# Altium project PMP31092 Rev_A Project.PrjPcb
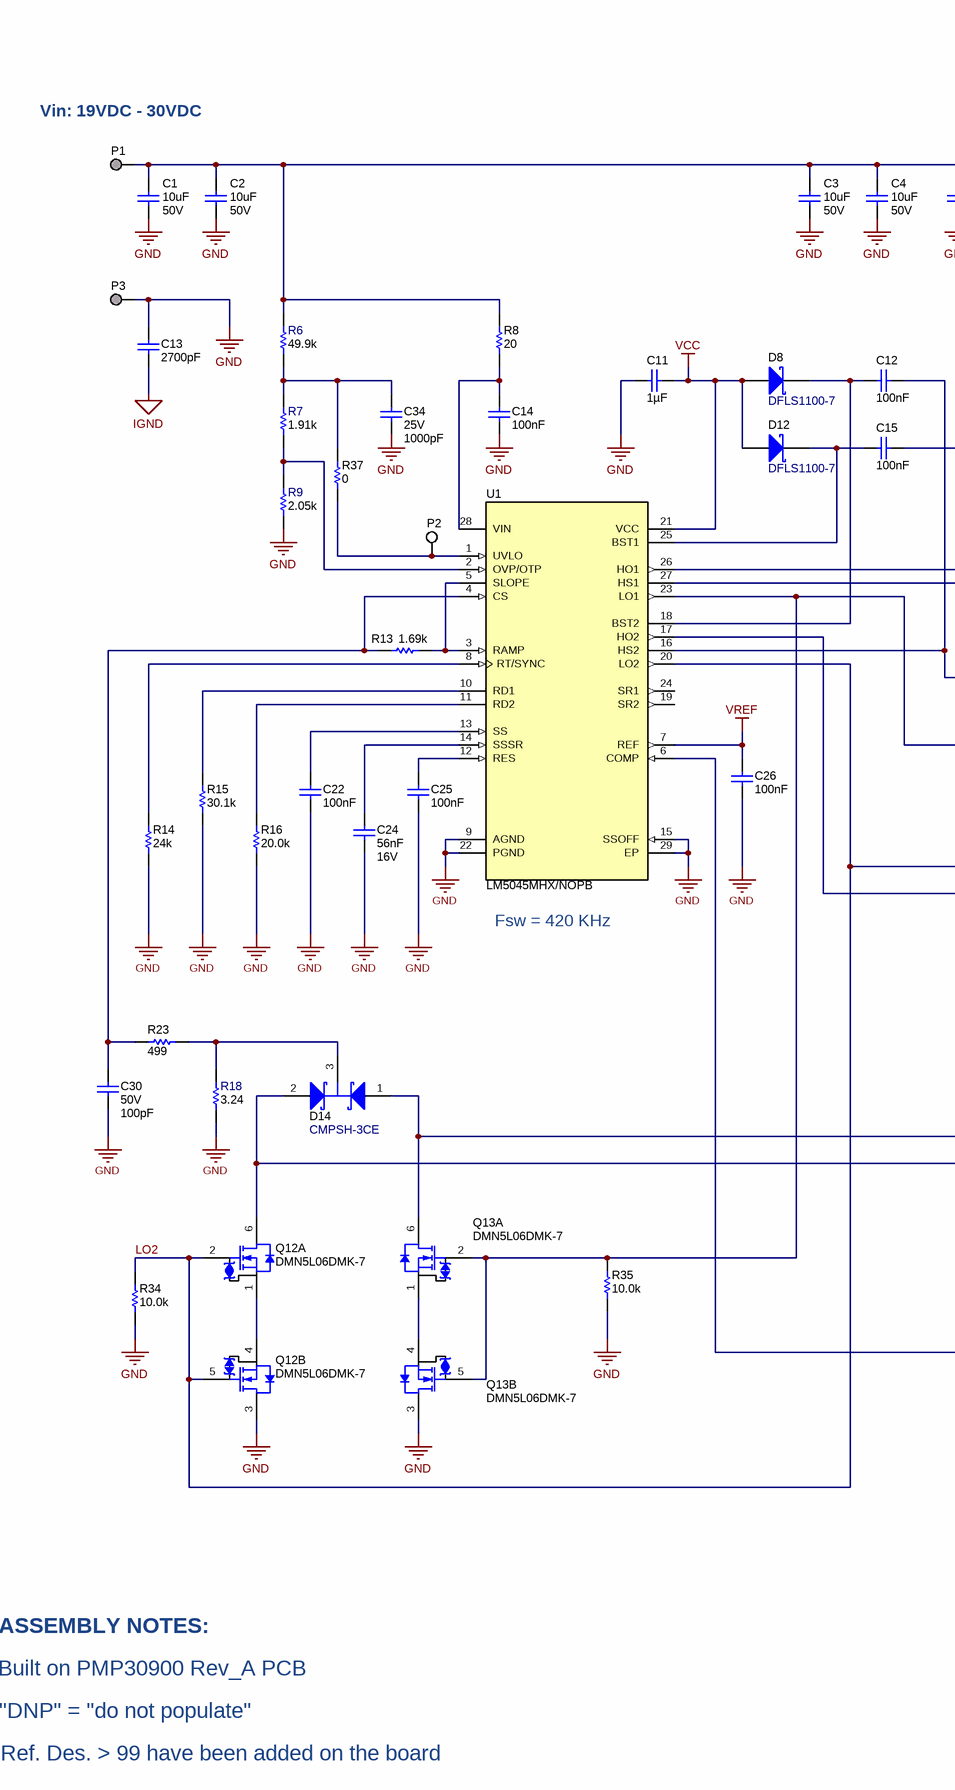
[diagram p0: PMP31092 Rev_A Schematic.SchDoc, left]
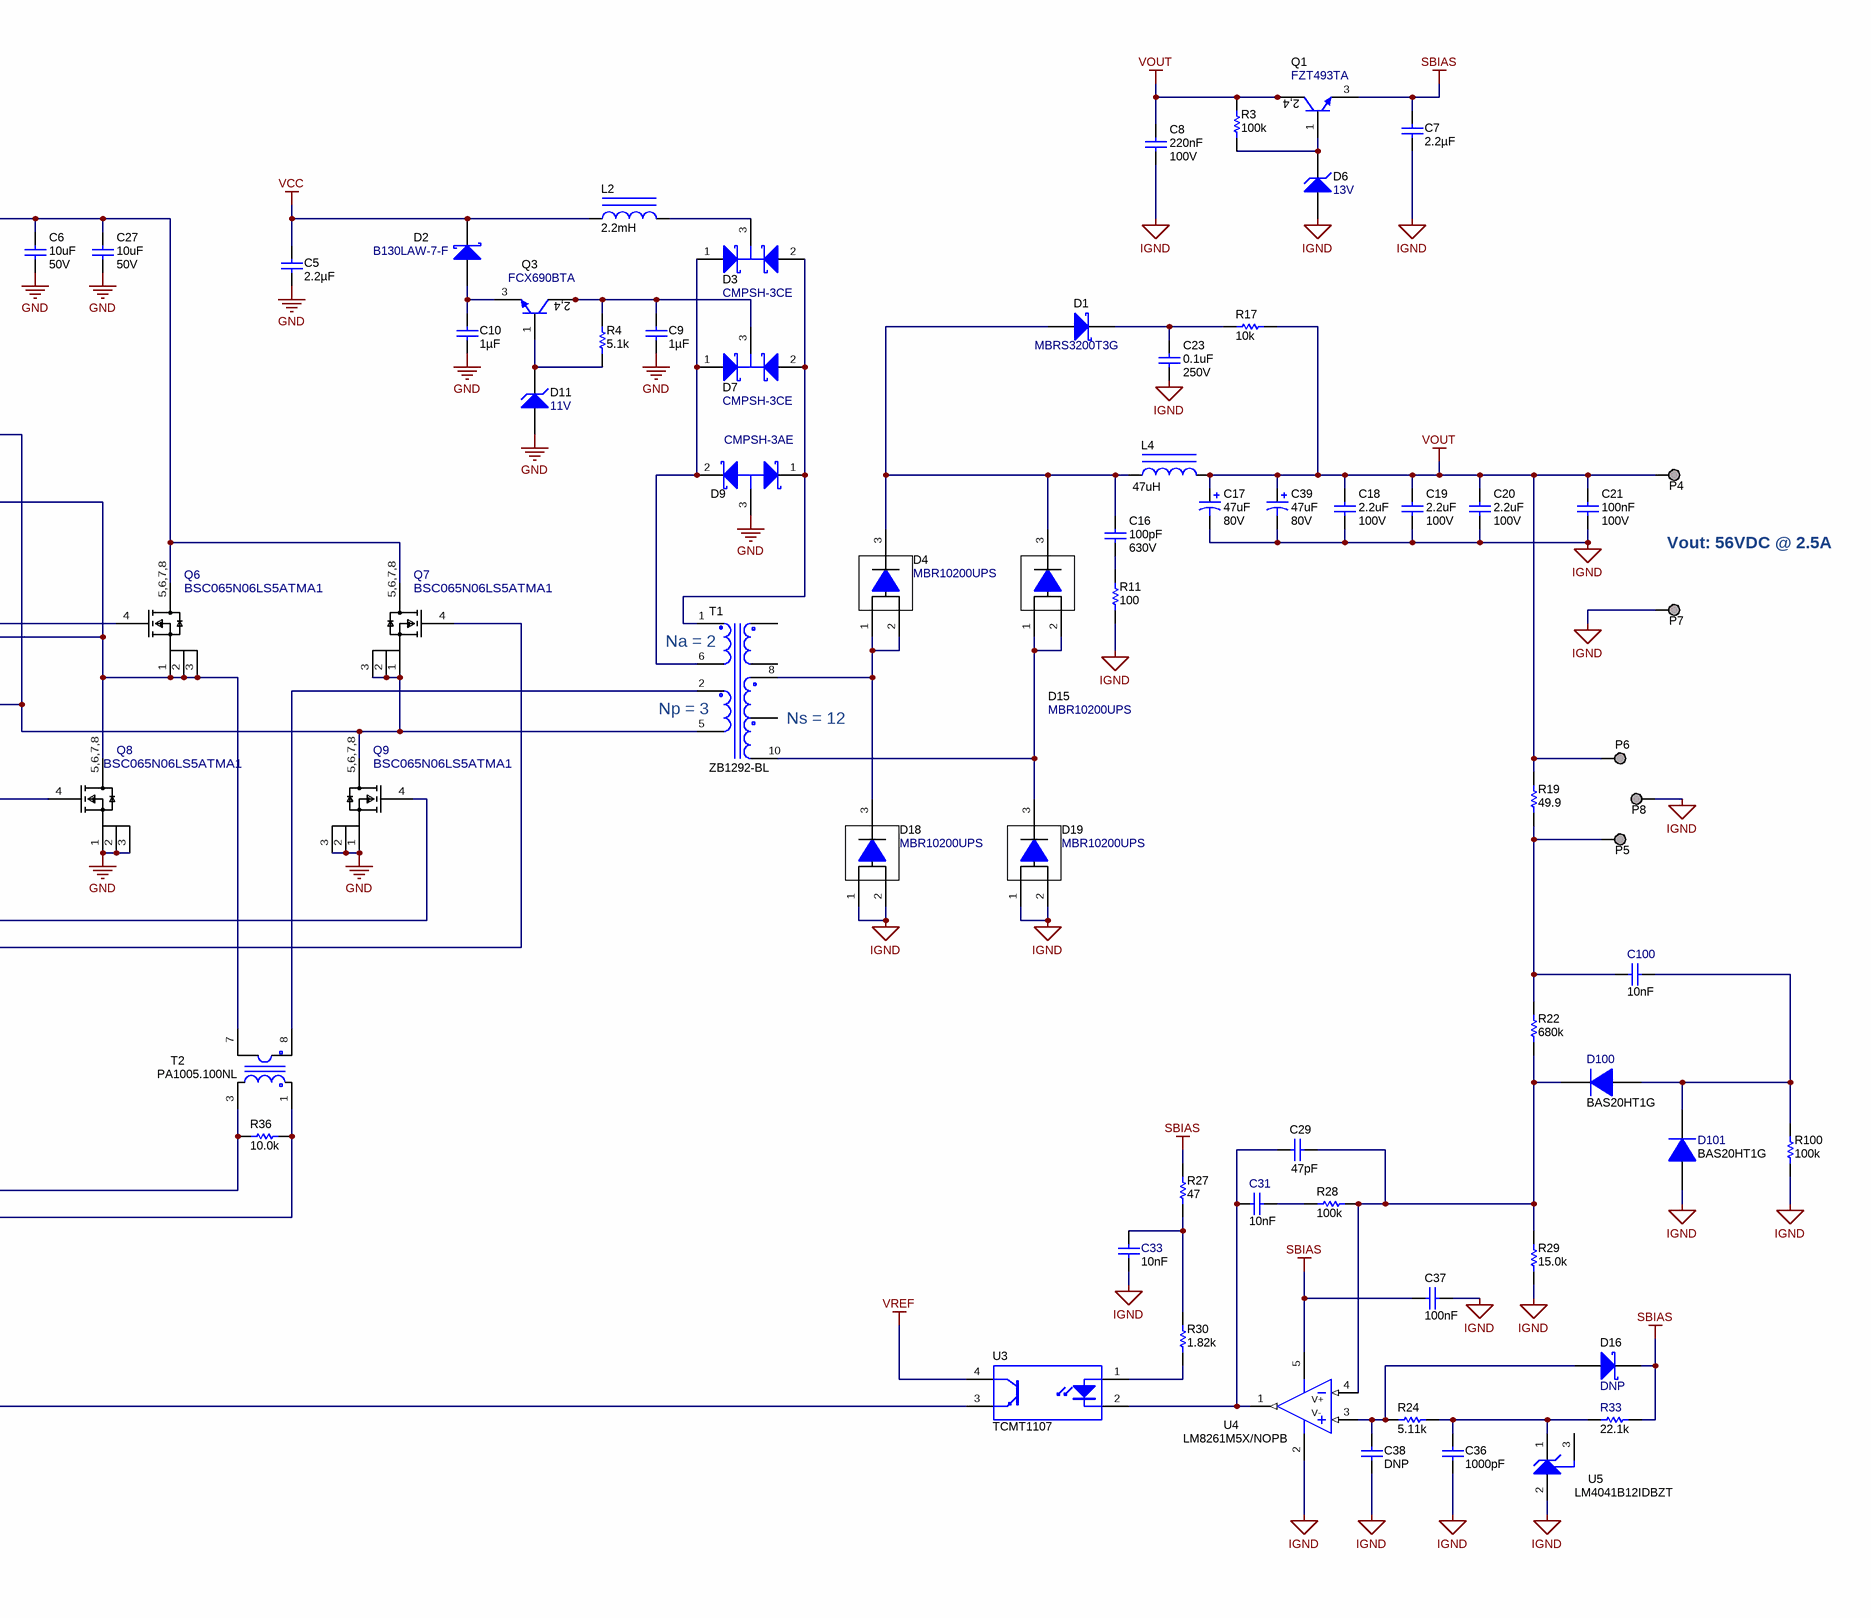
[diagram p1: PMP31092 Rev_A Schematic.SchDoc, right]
CopyrightYear: 2021; PCB_Layout: Renate Flesch; PCB_Rev: A; PRJ_Customer: Public Release; PRJ_Engineer: V. Levy / R. Scibilia; PRJ_Number: PMP31092; PRJ_Title: 18V-30Vin to 56V 140W Full Bridge; SCH_Rev: A; TechSupport: http://www.ti.com/support; TID: N/A
1 sheet, 105 parts. Net scope: global (net labels, ports and power ports of the same name join across sheets).
Board file: PMP30900 Rev_A PCB.PcbDoc

## Sheet PMP31092 Rev_A Schematic.SchDoc: 18V-30Vin to 56V 140W Full Bridge
size A2; Date: Not shown in title block; ApprovedBy: Not shown in title block; CheckedBy: Not shown in title block; Author: Not shown in title block; CompanyName: Not shown in title block; DrawnBy: V. Levy / R. Scibilia; Engineer: Not shown in title block; Organization: Not shown in title block; Address1: Not shown in title block; Address2: Not shown in title block; Address3: Not shown in title block; Address4: Not shown in title block; DocumentNumber: A; Revision: Use project parameter SCH_Rev; SheetNumber: 1; SheetTotal: 1; PageSetup: Record=PageOptions¦CenterHorizontal=True¦CenterVertical=True¦PrintScale=1.00¦XCorrection=1.00¦YCorrection=1.00¦PrintKind=0¦BorderSize=5000000¦LeftOffset=0¦BottomOffset=0¦Orientation=2¦PaperLength=1000¦PaperWidth=1000¦Scale=100¦PaperSource=15¦PrintQuality=600¦MediaType=1¦DitherType=10¦PaperKind=Letter¦PrintScaleMode=1

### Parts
C1  VDC_V: 50V  ValueDisplayed: 10uF  [1210_280]  (hidden comment: C3225X5R1H106K250AB)
C2  VDC_V: 50V  ValueDisplayed: 10uF  [1210_280]  (hidden comment: C3225X5R1H106K250AB)
C3  VDC_V: 50V  ValueDisplayed: 10uF  [1210_280]  (hidden comment: C3225X5R1H106K250AB)
C4  VDC_V: 50V  ValueDisplayed: 10uF  [1210_280]  (hidden comment: C3225X5R1H106K250AB)
C5  Cap_F: 2.2µF  [0805_HV]  (hidden comment: GRM21BR71C225KA12L)
C6  VDC_V: 50V  ValueDisplayed: 10uF  [1210_280]  (hidden comment: C3225X5R1H106K250AB)
C7  Cap_F: 2.2µF  [0805_HV]  (hidden comment: GRM21BR71E225KA73L)
C8  Cap_F: 220nF  VDC_V: 100V  [0805_HV]  (hidden comment: GRM21AR72A224KAC5L)
C9  Cap_F: 1µF  [0805_HV]  (hidden comment: GRM21BR71H105KA12L)
C10  Cap_F: 1µF  [0603]  (hidden comment: C1608X7R1C105K080AC)
C11  Cap_F: 1µF  [0603]  (hidden comment: C1608X7R1C105K080AC)
C12  Cap_F: 100nF  [0603]  (hidden comment: 06033C104KAT2A)
C13  ValueDisplayed: 2700pF  [1808]  (hidden comment: C1808C272KGRACTU)
C14  Cap_F: 100nF  [0603]  (hidden comment: GRM188R72A104KA35D)
C15  Cap_F: 100nF  [0603]  (hidden comment: 06033C104KAT2A)
C16  VDC_V: 630V  ValueDisplayed: 100pF  [1206]  (hidden comment: GRM31A5C2J101JW01D)
C17  VDC_V: 80V  ValueDisplayed: 47uF  [SM_RADIAL_10BMM]  (hidden comment: EEHZC1K470P)
C18  VDC_V: 100V  ValueDisplayed: 2.2uF  [1210_270]  (hidden comment: GRM32ER72A225KA35L)
C19  VDC_V: 100V  ValueDisplayed: 2.2uF  [1210_270]  (hidden comment: GRM32ER72A225KA35L)
C20  VDC_V: 100V  ValueDisplayed: 2.2uF  [1210_270]  (hidden comment: GRM32ER72A225KA35L)
C21  Cap_F: 100nF  VDC_V: 100V  [0805_HV]  (hidden comment: C0805C104K1RACTU)
C22  Cap_F: 100nF  [0603]  (hidden comment: 06033C104KAT2A)
C23  VDC_V: 250V  ValueDisplayed: 0.1uF  [1206_180]  (hidden comment: GRM31CR72E104KW03L)
C24  Cap_F: 56nF  VDC_V: 16V  [0603]  (hidden comment: GRM188R71C563KA01D)
C25  Cap_F: 100nF  [0603]  (hidden comment: 06033C104KAT2A)
C26  Cap_F: 100nF  [0603]  (hidden comment: 06033C104KAT2A)
C27  VDC_V: 50V  ValueDisplayed: 10uF  [1210_280]  (hidden comment: C3225X5R1H106K250AB)
C29  ValueDisplayed: 47pF  [0603]  (hidden comment: GRM1885C1H470JA01D)
C30  VDC_V: 50V  ValueDisplayed: 100pF  [0603]  (hidden comment: C1608C0G1H101J080AE)
C31  Cap_F: 10nF  [0603]  (hidden comment: C0603C103J1RACTU)
C33  Cap_F: 10nF  [0603]  (hidden comment: C0603C103J1RACTU)
C34  VDC_V: 25V  ValueDisplayed: 1000pF  [0603]  (hidden comment: GRM1885C1E102JA01D)
C36  ValueDisplayed: 1000pF  [0603]  (hidden comment: GRM1885C1E102JA01D)
C37  Cap_F: 100nF  [0603]  (hidden comment: 06033C104KAT2A)
C38  DNP  [0603]
C39  VDC_V: 80V  ValueDisplayed: 47uF  [SM_RADIAL_10BMM]  (hidden comment: EEHZC1K470P)
C100  Cap_F: 10nF  [0603]  (hidden comment: C0603C103J1RACTU)
D1  MBRS3200T3G  [SMB]
D2  B130LAW-7-F  [SOD-123]
D3  CMPSH-3CE  [SOT-23]
D4  MBR10200UPS  [TO-277]
D6  value 13V  [SOD-123]  (hidden comment: MMSZ5243B-7-F)
D7  CMPSH-3CE  [SOT-23]
D8  DFLS1100-7  [PowerDI123]
D9  CMPSH-3AE  [SOT-23]
D11  value 11V  [SOD-123]  (hidden comment: MMSZ5241B-7-F)
D12  DFLS1100-7  [PowerDI123]
D14  CMPSH-3CE  [SOT-23]
D15  MBR10200UPS  [TO-277]
D16  DNP  [SOD-323]
D18  MBR10200UPS  [TO-277]
D19  MBR10200UPS  [TO-277]
D100  BAS20HT1G  [SOD-323]
D101  BAS20HT1G  [SOD-323]
L2  ValueDisplayed: 2.2mH  [LPS5030]  (hidden comment: LPS5030-225MLB)
L4  value 47uH  [SER2211]  (hidden comment: SER2211-473MED)
P1  3104-2-00-34-00-00-08-0  [3104-2]  (value not drawn)
P2  5015  [Testpoint_Keystone_Miniature]  (value not drawn)
P3  3104-2-00-34-00-00-08-0  [3104-2]  (value not drawn)
P4  3231-2-00-34-00-00-08-0  [3231-2]  (value not drawn)
P5  3104-2-00-34-00-00-08-0  [3104-2]  (value not drawn)
P6  3104-2-00-34-00-00-08-0  [3104-2]  (value not drawn)
P7  3231-2-00-34-00-00-08-0  [3231-2]  (value not drawn)
P8  3104-2-00-34-00-00-08-0  [3104-2]  (value not drawn)
Q1  FZT493TA  [SOT-223]
Q3  FCX690BTA  [SOT-89-3]
Q6  BSC065N06LS5ATMA1  [FP-BSC065N06LS5ATMA1_SuperSO8-Recommended_Land_Pattern]
Q7  BSC065N06LS5ATMA1  [FP-BSC065N06LS5ATMA1_SuperSO8-Recommended_Land_Pattern]
Q8  BSC065N06LS5ATMA1  [FP-BSC065N06LS5ATMA1_SuperSO8-Recommended_Land_Pattern]
Q9  BSC065N06LS5ATMA1  [FP-BSC065N06LS5ATMA1_SuperSO8-Recommended_Land_Pattern]
Q12  DMN5L06DMK-7  [SOT-26]  (parts A,B of 2)
Q13  DMN5L06DMK-7  [SOT-26]  (parts A,B of 2)
R3  ValueDisplayed: 100k  [0805_HV]  (hidden comment: ERJ-6GEYJ104V)
R4  ValueDisplayed: 5.1k  [0805_HV]  (hidden comment: ERJ-6GEYJ512V)
R6  ValueDisplayed: 49.9k  [0805_HV]  (hidden comment: ERJ-6ENF4992V)
R7  ValueDisplayed: 1.91k  [0603]  (hidden comment: CRCW06031K91FKEA)
R8  ValueDisplayed: 20  [0805_HV]  (hidden comment: ERJ-6GEYJ200V)
R9  ValueDisplayed: 2.05k  [0603]  (hidden comment: RC0603FR-072K05L)
R11  ValueDisplayed: 100  [2010]  (hidden comment: CRCW2010100RJNEF)
R13  ValueDisplayed: 1.69k  [0603]  (hidden comment: CRCW06031K69FKEA)
R14  ValueDisplayed: 24k  [0603]  (hidden comment: CRCW060324K0JNEA)
R15  ValueDisplayed: 30.1k  [0603]  (hidden comment: CRCW060330K1FKEA)
R16  ValueDisplayed: 20.0k  [0603]  (hidden comment: CRCW060320K0FKEA)
R17  ValueDisplayed: 10k  [2512]  (hidden comment: CRCW251210K0JNEG)
R18  ValueDisplayed: 3.24  [0805_HV]  (hidden comment: RC0805FR-073R24L)
R19  ValueDisplayed: 49.9  [0603]  (hidden comment: ERJ-3EKF49R9V)
R22  ValueDisplayed: 680k  [0603]  (hidden comment: RC0603FR-07680KL)
R23  ValueDisplayed: 499  [0603]  (hidden comment: CRCW0603499RFKEA)
R24  ValueDisplayed: 5.11k  [0603]  (hidden comment: CRCW06035K11FKEA)
R27  ValueDisplayed: 47  [0603]  (hidden comment: CRCW060347R0JNEAHP)
R28  ValueDisplayed: 100k  [0603]  (hidden comment: RC0603FR-07100KL)
R29  ValueDisplayed: 15.0k  [0603]  (hidden comment: CRCW060315K0FKEA)
R30  ValueDisplayed: 1.82k  [0603]  (hidden comment: CRCW06031K82FKEA)
R33  ValueDisplayed: 22.1k  [0603]  (hidden comment: RC0603FR-0722K1L)
R34  ValueDisplayed: 10.0k  [0603]  (hidden comment: CRCW060310K0FKEA)
R35  ValueDisplayed: 10.0k  [0603]  (hidden comment: CRCW060310K0FKEA)
R36  ValueDisplayed: 10.0k  [0603]  (hidden comment: CRCW060310K0FKEA)
R37  ValueDisplayed: 0  [0603]  (hidden comment: CRCW06030000Z0EA)
R100  ValueDisplayed: 100k  [0603]  (hidden comment: RC0603FR-07100KL)
T1  ZB1292-BL  [PA0876]
T2  PA1005.100NL  [P82xx]
U1  LM5045MHX/NOPB  [PWP0028A_N]
U3  TCMT1107  [SOP-4]
U4  LM8261M5X/NOPB  [DBV0005A_N]
U5  LM4041B12IDBZT  [DBZ0003A_N]

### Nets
GND: C1.2 C2.2 C3.2 C4.2 C5.2 C6.2 C9.2 C10.2 C11.2 C13.1 C14.2 C22.2 C24.2 C25.2 C26.2 C27.2 C30.2 C34.2 D9.3(A) D11.2(A) P3.1 Q8.1(S) Q8.2(S) Q8.3(S) Q9.1(S) Q9.2(S) Q9.3(S) Q12.3(D) Q13.3(D) R9.1 R14.1 R15.1 R16.1 R18.1 R34.1 R35.1 U1.9(AGND) U1.15(SSOFF) U1.22(PGND) U1.29(EP)
IGND: C7.2 C8.2 C13.2 C17.2(-) C18.2 C19.2 C20.2 C21.2 C23.2 C33.2 C36.2 C37.1 C38.2 C39.2(-) D6.2(A) D18.1(A) D18.2(A) D19.1(A) D19.2(A) D101.2(A) P7.1 P8.1 R11.1 R29.2 R100.1 U4.2(V-) U5.2(ANODE)
SBIAS: C7.1 C37.2 D16.1(K) Q1.3(E) R27.2 R33.1 U4.5(V+)
VCC: C5.1 C11.1 D2.1(K) D8.2(A) D12.2(A) L2.1 U1.21(VCC)
VOUT: C8.1 C17.1(+) C18.1 C19.1 C20.1 C21.1 C39.1(+) L4.1 P4.1 P6.1 Q1.2(C) Q1.4(C) R3.2 R17.2 R19.2
VREF: C26.1 U1.7(REF) U3.4(C)
LO2: Q9.4(G) Q12.2(G) Q12.5(G) R34.2 U1.20(LO2)
NetC1_1: C1.1 C2.1 C3.1 C4.1 C6.1 C27.1 P1.1 Q6.5,6,7,8(D) Q7.5,6,7,8(D) R6.2 R8.2
NetC9_1: C9.1 D7.3(K) Q3.2(C) Q3.4(C) R4.2
NetC10_1: C10.1 D2.2(A) Q3.3(E)
NetC12_1: C12.1 Q7.1(S) Q7.2(S) Q7.3(S) Q9.5,6,7,8(D) T1.5 U1.16(HS2)
NetC12_2: C12.2 D8.1(K) U1.18(BST2)
NetC14_1: C14.1 R8.1 U1.28(VIN)
NetC15_1: C15.1 Q6.1(S) Q6.2(S) Q6.3(S) Q8.5,6,7,8(D) T2.7 U1.27(HS1)
NetC15_2: C15.2 D12.1(K) U1.25(BST1)
NetC16_1: C16.1 D1.2(A) D4.3(K) D15.3(K) L4.2
NetC16_2: C16.2 R11.2
NetC22_1: C22.1 U1.13(SS)
NetC23_1: C23.1 D1.1(K) R17.1
NetC24_1: C24.1 U1.14(SSSR)
NetC25_1: C25.1 U1.12(RES)
NetC29_1: C29.1 D100.1(K) R22.1 R28.2 R29.1 U4.4(IN-)
NetC29_2: C29.2 C31.1 U3.2(K) U4.1(OUT)
NetC30_1: C30.1 R13.1 R23.1 U1.4(CS)
NetC31_2: C31.2 R28.1
NetC33_1: C33.1 R27.1 R30.2
NetC34_1: C34.1 R6.1 R7.2 R37.2
NetC36_1: C36.1 R24.2 R33.2 U5.1(CATHODE)
NetC38_1: C38.1 D16.2(A) R24.1 U4.3(IN+)
NetC100_1: C100.1 P5.1 R19.1 R22.2
NetC100_2: C100.2 D100.2(A) D101.1(K) R100.2
NetD3_1: D3.1(A1) D7.1(A1) D9.2(K2) T1.6
NetD3_2: D3.2(A2) D7.2(A2) D9.1(K1) T1.1
NetD3_3: D3.3(K) L2.2
NetD4_1: D4.1(A) D4.2(A) D18.3(K) T1.8
NetD6_1: D6.1(K) Q1.1(B) R3.1
NetD11_1: D11.1(K) Q3.1(B) R4.1
NetD14_1: D14.1(A1) Q13.6(D) R36.1 T2.3
NetD14_2: D14.2(A2) Q12.6(D) R36.2 T2.1
NetD14_3: D14.3(K) R18.2 R23.2
NetD15_1: D15.1(A) D15.2(A) D19.3(K) T1.10
NetP2_1: P2.1 R37.1 U1.1(UVLO)
NetQ6_4: Q6.4(G) U1.26(HO1)
NetQ7_4: Q7.4(G) U1.17(HO2)
NetQ8_4: Q8.4(G) Q13.2(G) Q13.5(G) R35.2 U1.23(LO1)
NetQ12_1: Q12.1(S) Q12.4(S)
NetQ13_1: Q13.1(S) Q13.4(S)
NetR7_1: R7.1 R9.2 U1.2(OVP/OTP)
NetR13_2: R13.2 U1.3(RAMP) U1.5(SLOPE)
NetR14_2: R14.2 U1.8(RT/SYNC)
NetR15_2: R15.2 U1.10(RD1)
NetR16_2: R16.2 U1.11(RD2)
NetR30_1: R30.1 U3.1(A)
NetT1_2: T1.2 T2.8
NetU1_6: U1.6(COMP) U3.3(E)

Not connected (* = marked no-connect by the designer): T1 7 9 11; U1 19(SR2) 24(SR1); U5 3(NC)

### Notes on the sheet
- (near P1) Vin: 19VDC - 30VDC
- Vout: 56VDC @ 2.5A
- (near T1) Na = 2
- (near T1) Np = 3
- (near T1) Ns = 12
- Fsw = 420 KHz
- ASSEMBLY NOTES:
- Built on PMP30900 Rev_A PCB
- "DNP" = "do not populate"
- Ref. Des. > 99 have been added on the board

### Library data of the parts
C1-C4 C6 C27 = CMP-0009103-2: CAP, CERM, 10 uF, 50 V, +/- 10%, X5R, 1210; Manufacturer: TDK; TaMin_C: -55°C; Polarized: N; SizeAreaWB_mm2: 14.7; Value1: Unknown; U/M: EA; Value: 10uF; TaMax_C: 85°C; SizeZ_mm: 2.8; SizeX_mm: 3.2; SizeY_mm: 2.5; Cap_Case: 1210; SizeArea_mm2: 8; Cap_F: 10µF; AEC Category: Q200
C5 = CMP-0008329-2: CAP, CERM, 2.2 uF, 16 V, +/- 10%, X7R, 0805; Manufacturer: MuRata; TaMin_C: -55°C; ESR_ohm: 4m; Polarized: N; SizeAreaWB_mm2: 6.75; Value1: 0.004 ohm; U/M: EA; Value: 2.2uF; TaMax_C: 125°C; SizeZ_mm: 1.45; SizeX_mm: 2; SizeY_mm: 1.25; Cap_Case: 0805; Value2: 16V; SizeArea_mm2: 2.5; AEC Category: Q200
C7 = CMP-0008342-2: CAP, CERM, 2.2 uF, 25 V, +/- 10%, X7R, 0805; Manufacturer: MuRata; TaMin_C: -55°C; ESR_ohm: 5m; Polarized: N; SizeAreaWB_mm2: 6.75; Value1: 0.005 ohm; U/M: EA; Value: 2.2uF; TaMax_C: 125°C; SizeZ_mm: 1.45; SizeX_mm: 2; SizeY_mm: 1.25; Cap_Case: 0805; Value2: 25V; SizeArea_mm2: 2.5; AEC Category: Q200
C8 = CMP-0008249-2: CAP, CERM, 0.22 uF, 100 V, +/- 10%, X7R, 0805; Manufacturer: MuRata; TaMin_C: -55°C; Polarized: N; SizeAreaWB_mm2: 6.75; Value1: Unknown; U/M: EA; Value: 0.22uF; TaMax_C: 125°C; SizeZ_mm: 1.45; SizeX_mm: 2; SizeY_mm: 1.25; Cap_Case: 0805; SizeArea_mm2: 2.5; AEC Category: Q200
C9 = CMP-0008350-2: CAP, CERM, 1 uF, 50 V, +/- 10%, X7R, 0805; Manufacturer: MuRata; TaMin_C: -55°C; Polarized: N; SizeAreaWB_mm2: 6.75; Value1: Unknown; U/M: EA; Value: 1uF; TaMax_C: 125°C; SizeZ_mm: 1.45; SizeX_mm: 2; SizeY_mm: 1.25; Cap_Case: 0805; Value2: 50V; SizeArea_mm2: 2.5; AEC Category: Q200
C10 C11 = CMP-0007037-4: CAP, CERM, 1 uF, 16 V, +/- 10%, X7R, 0603; Manufacturer: TDK; TaMin_C: -55°C; ESR_ohm: 5.7m; Polarized: N; SizeAreaWB_mm2: 4.68; Value1: 0.0057 ohm; U/M: EA; Value: 1uF; TaMax_C: 125°C; SizeZ_mm: 1; SizeX_mm: 1.6; SizeY_mm: 0.8; Value2: 16V; SizeArea_mm2: 1.28; AEC Category: Q200
C12 C15 C22 C25 C26 C37 = CMP-0006753-4: CAP, CERM, 0.1 uF, 25 V, +/- 10%, X7R, 0603; Manufacturer: AVX; TaMin_C: -55°C; ESR_ohm: 50m; Polarized: N; SizeAreaWB_mm2: 4.68; Value1: 0.05 ohm; U/M: EA; Value: 0.1uF; TaMax_C: 125°C; SizeZ_mm: 1; SizeX_mm: 1.6; SizeY_mm: 0.8; Value2: 25V; SizeArea_mm2: 1.28; AEC Category: Q200
C13 = CMP-0009316-2: CAP, CERM, 2700 pF, 2000 V, +/- 10%, X7R, 1808; Manufacturer: Kemet; TaMin_C: -55°C; Polarized: N; SizeAreaWB_mm2: 16.5; Value1: Unknown; U/M: EA; Value: 2700pF; TaMax_C: 125°C; SizeZ_mm: 2.03; SizeX_mm: 4.5; SizeY_mm: 2; Value2: 2000V; SizeArea_mm2: 9; Cap_F: 2.7nF; VDC_V: 2kV; AEC Category: Q200
C14 = CMP-0007469-4: CAP, CERM, 0.1 uF, 100 V, +/- 10%, X7R, 0603; Manufacturer: MuRata; TaMin_C: -55°C; Polarized: N; SizeAreaWB_mm2: 4.68; Value1: Unknown; U/M: EA; Value: 0.1uF; TaMax_C: 125°C; SizeZ_mm: 1; SizeX_mm: 1.6; SizeY_mm: 0.8; Value2: 100V; SizeArea_mm2: 1.28; AEC Category: Q200
C16 = CMP-0008884-2: CAP, CERM, 100 pF, 630 V, +/- 5%, C0G/NP0, 1206; Manufacturer: MuRata; TaMin_C: -55°C; Polarized: N; SizeAreaWB_mm2: 10.92; Value1: Unknown; U/M: EA; Value: 100pF; TaMax_C: 125°C; SizeZ_mm: 1.35; SizeX_mm: 3.2; SizeY_mm: 1.6; SizeArea_mm2: 5.12; AEC Category: Q200
C17 C39 = CMP-0012606-3: CAP, Polymer Hybrid, 47 uF, 80 V, +/- 20%, 36 mohm, 10x10 SMD; Manufacturer: Panasonic; TaMin_C: -55°C; ESR_ohm: 20; Polarized: Y; SizeAreaWB_mm2: 159.9; Value1: 36 mohm; Value: 47uF; TaMax_C: 125°C; SizeZ_mm: 10.2; SizeX_mm: 11; SizeY_mm: 10.3; SizeArea_mm2: 113.3; CompType: Capacitor; Cap_F: 270µF; IRMS_A: 2A; AEC Category: Q200
C18-C20 = CMP-0009232-2: CAP, CERM, 2.2 uF, 100 V, +/- 10%, X7R, 1210; Manufacturer: MuRata; TaMin_C: -55°C; ESR_ohm: 7m; Polarized: N; SizeAreaWB_mm2: 14.7; Value1: 0.007 ohm; U/M: EA; Value: 2.2uF; TaMax_C: 125°C; SizeZ_mm: 2.7; SizeX_mm: 3.2; SizeY_mm: 2.5; Cap_Case: 1210; SizeArea_mm2: 8; Cap_F: 2.2µF; IRMS_A: 4.4A; AEC Category: Q200
C21 = CMP-0007722-2: CAP, CERM, 0.1 uF, 100 V, +/- 10%, X7R, 0805; Manufacturer: Kemet; TaMin_C: -55°C; ESR_ohm: 64m; Polarized: N; SizeAreaWB_mm2: 6.75; Value1: 0.064 ohm; U/M: EA; Value: 0.1uF; TaMax_C: 125°C; SizeZ_mm: 1.45; SizeX_mm: 2; SizeY_mm: 1.25; Cap_Case: 0805; SizeArea_mm2: 2.5; IRMS_A: 1.64A; AEC Category: Q200
C23 = CMP-0008973-2: CAP, CERM, 0.1 uF, 250 V, +/- 10%, X7R, 1206; Manufacturer: MuRata; TaMin_C: -55°C; Polarized: N; SizeAreaWB_mm2: 10.92; Value1: Unknown; U/M: EA; Value: 0.1uF; TaMax_C: 125°C; SizeZ_mm: 1.8; SizeX_mm: 3.2; SizeY_mm: 1.6; Cap_Case: 1206; SizeArea_mm2: 5.12; Cap_F: 100nF; AEC Category: Q200
C24 = CMP-0007399-4: CAP, CERM, 0.056 uF, 16 V, +/- 10%, X7R, 0603; Manufacturer: MuRata; TaMin_C: -55°C; Polarized: N; SizeAreaWB_mm2: 4.68; Value1: Unknown; U/M: EA; TaMax_C: 125°C; SizeZ_mm: 1; SizeX_mm: 1.6; SizeY_mm: 0.8; SizeArea_mm2: 1.28; AEC Category: Q200
C29 = CMP-0007220-4: CAP, CERM, 47 pF, 50 V, +/- 5%, C0G/NP0, 0603; Manufacturer: MuRata; TaMin_C: -55°C; Polarized: N; SizeAreaWB_mm2: 4.68; Value1: Unknown; U/M: EA; Value: 47pF; TaMax_C: 125°C; SizeZ_mm: 1; SizeX_mm: 1.6; SizeY_mm: 0.8; Value2: 50V; SizeArea_mm2: 1.28; AEC Category: Q200
C30 = CMP-0006989-4: CAP, CERM, 100 pF, 50 V, +/- 5%, C0G/NP0, 0603; Manufacturer: TDK; TaMin_C: -55°C; Polarized: N; SizeAreaWB_mm2: 4.68; Value1: Unknown; U/M: EA; Value: 100pF; TaMax_C: 125°C; SizeZ_mm: 1; SizeX_mm: 1.6; SizeY_mm: 0.8; SizeArea_mm2: 1.28; AEC Category: Q200
C31 C33 C100 = CMP-0006848-4: CAP, CERM, 0.01 uF, 100 V, +/- 5%, X7R, 0603; Manufacturer: Kemet; TaMin_C: -55°C; Polarized: N; SizeAreaWB_mm2: 4.68; Value1: Unknown; U/M: EA; Value: 0.01uF; TaMax_C: 125°C; SizeZ_mm: 1; SizeX_mm: 1.6; SizeY_mm: 0.8; Value2: 100V; SizeArea_mm2: 1.28; AEC Category: Q200
C34 = CMP-0007159-4: CAP, CERM, 1000 pF, 25 V, +/- 5%, C0G/NP0, 0603; Manufacturer: MuRata; TaMin_C: -55°C; Polarized: N; SizeAreaWB_mm2: 4.68; Value1: Unknown; U/M: EA; Value: 1000pF; TaMax_C: 125°C; SizeZ_mm: 1; SizeX_mm: 1.6; SizeY_mm: 0.8; SizeArea_mm2: 1.28; Cap_F: 1nF; AEC Category: Q200
C36 = CMP-0007159-4: CAP, CERM, 1000 pF, 25 V, +/- 5%, C0G/NP0, 0603; Manufacturer: MuRata; TaMin_C: -55°C; Polarized: N; SizeAreaWB_mm2: 4.68; Value1: Unknown; U/M: EA; Value: 1000pF; TaMax_C: 125°C; SizeZ_mm: 1; SizeX_mm: 1.6; SizeY_mm: 0.8; Value2: 25V; SizeArea_mm2: 1.28; Cap_F: 1nF; AEC Category: Q200
C38 = CMP-0007364-4: Manufacturer: MuRata; TaMin_C: -55°C; Polarized: N; TempCo: X7R; SizeAreaWB_mm2: 4.68; Value1: Unknown; U/M: EA; TaMax_C: 125°C; Tolerance_%: 10%; SizeZ_mm: 1; SizeX_mm: 1.6; SizeY_mm: 0.8; Value2: 6.3V; SizeArea_mm2: 1.28; AEC Category: Q200
D1 = CMP-0028599-2: Diode, Schottky, 200 V, 3 A, SMB; Manufacturer: ON Semiconductor; Io_A: 3A; SizeY_mm: 3.81; RJC_CperW: 62; SizeX_mm: 5.6; TJmax_C: 175°C; Vf_V: 840mV; SizeZ_mm: 2.6; Green_REACh: Incomplete; Vr_V: 200V; Green_Lifecycle: Not Set; AEC Category: Q101; SizeAreaWB_mm2: 44.156; Value2: 0.84V; SizeArea_mm2: 21.336
D2 = CMP-0028382-2: Diode, Schottky, 30 V, 1 A, SOD-123; Manufacturer: Diodes Inc.; SizeX_mm: 3.85; AEC Category: Q101; SizeAreaWB_mm2: 13.095; SizeZ_mm: 1.35; TJmax_C: 125°C; Value2: 0.38V; SizeY_mm: 1.7; Value1: 1A; Green_REACh: Passed; Vr_V: 30V; Vf_V: 380mV; SizeArea_mm2: 6.545; Green_Lifecycle: Active
D3 D7 D14 = CMP-0028514-2: Diode, Schottky, 40 V, 0.2 A, SOT-23; Manufacturer: Central Semiconductor; Green_Lifecycle: Not Set; SizeX_mm: 2.5; TJmax_C: 150°C; Value2: 0.65V; SizeAreaWB_mm2: 14; SizeArea_mm2: 7.5; SizeZ_mm: 1.1; Vr_V: 40V; Green_REACh: Incomplete; Io_A: 200mA; SizeY_mm: 3; AEC Category: Q101; Value1: 0.2A; Vf_V: 650mV
D4 D15 D18 D19 = CMP-0750173-1: Diode, Schottky, 200 V, 10 A, TO-277B; Manufacturer: MCC; Value1: 10A; SizeZ_mm: 1.35; SizeX_mm: 4; AEC Category: Q101; Vr_V: 200V; SizeAreaWB_mm2: 51; SizeArea_mm2: 26; TJmax_C: 150°C; AEC Qualified: N; Value2: 0.67V; SizeY_mm: 6.5; Vf_V: 670mV
D6 = CMP-0005752-4: Diode, Zener, 13 V, 500 mW, SOD-123; Manufacturer: Diodes Inc.; Value1: 0.5W; SizeAreaWB_mm2: 13.095; RJA_CperW: 350; AEC Category: Q101; SizeZ_mm: 1.35; SizeX_mm: 3.85; Power_W: 500mW; SizeArea_mm2: 6.545; SizeY_mm: 1.7
D8 D12 = CMP-0028516-2: Diode, Schottky, 100 V, 1 A, PowerDI123; Manufacturer: Diodes Inc.; SizeY_mm: 1.78; SizeArea_mm2: 6.586; Io_A: 1A; SizeAreaWB_mm2: 13.066; TJmax_C: 175°C; Green_REACh: Passed; Vf_V: 770mV; RJC_CperW: 7; Vr_V: 100V; Green_Lifecycle: Active; SizeX_mm: 3.7; AEC Category: Q101; SizeZ_mm: 0.98; Value2: 0.77V
D9 = CMP-0028513-2: Diode, Schottky, 40 V, 0.2 A, SOT-23; Manufacturer: Central Semiconductor; SizeArea_mm2: 7.5; Green_Lifecycle: Not Set; AEC Category: Q101; Vr_V: 40V; Value2: 0.65V; SizeY_mm: 3; TJmax_C: 150°C; SizeZ_mm: 1.1; Value1: 0.2A; SizeX_mm: 2.5; Green_REACh: Incomplete; SizeAreaWB_mm2: 14; Io_A: 200mA; Vf_V: 650mV
D11 = CMP-0005750-4: Diode, Zener, 11 V, 500 mW, SOD-123; Manufacturer: Diodes Inc.; SizeArea_mm2: 6.545; RJA_CperW: 350; AEC Category: Q101; SizeX_mm: 3.85; SizeY_mm: 1.7; Value1: 0.5W; Power_W: 500mW; SizeAreaWB_mm2: 13.095; SizeZ_mm: 1.35
D16 = CMP-0028458-2: Manufacturer: Diodes Inc.; SizeArea_mm2: 3.645; Green_Lifecycle: Active; Io_A: 200mA; TJmax_C: 125°C; Value2: 0.7V; Vf_V: 700mV; Green_REACh: Passed; Value1: 0.2A; Type: Schottky; Vr_V: 30V; AEC Category: Q101; SizeAreaWB_mm2: 8.695; CompType: Diode; SizeY_mm: 1.35; SizeX_mm: 2.7; SizeZ_mm: 1
D100 D101 = CMP-0029150-2: Diode, Switching, 200 V, 0.2 A, AEC-Q101, SOD-323; Manufacturer: ON Semiconductor; Value2: 1.25V; Value1: 0.2A; SizeZ_mm: 1; Green_REACh: Incomplete; SizeArea_mm2: 3.645; Vr_V: 200V; SizeX_mm: 2.7; TJmax_C: 150°C; Io_A: 200mA; Green_Lifecycle: Not Set; SizeAreaWB_mm2: 8.695; AEC Qualified: Y; AEC Category: Q101; SizeY_mm: 1.35
L2 = CMP-0062000-2: Inductor, Shielded Drum Core, Ferrite, 2.2 mH, 0.08 A, 11 ohm, SMD; Manufacturer: Coilcraft; Isat: 0.08A @ 30% inductance drop; Irms: 0.15A @ 40C rise; Green_Lifecycle: Not Set; SizeAreaWB_mm2: 33.64; DCR_ohm: 11; Green_REACh: Incomplete; Value1: 11 ohm; Value: 2.2mH; Imax_A: 80mA; SizeZ_mm: 2.9; SizeX_mm: 4.8; Value2: 0.08A; SizeArea_mm2: 23.04; AEC Category: Q200
L4 = SER2211-473: Inductor, Shielded E Core, Ferrite, 47 uH, 4.4 A, 0.0107 ohm, SMD; Manufacturer: Coilcraft; Value: 47uH; Isat: 4.4A @ 10% inductance drop; Irms: 10.6A @ 40C rise; Green_Lifecycle: Not Set; SizeAreaWB_mm2: 438.426; DCR_ohm: 10.7m; Green_REACh: Incomplete; Imax_A: 10.6A; SizeZ_mm: 10.5; SizeX_mm: 19.2; SizeY_mm: 22.5; Value2: 4.4A; SizeArea_mm2: 358.666; Ind_H: 47µH; AEC Category: Q200
P1 P3 P5 P6 P8 = CMP-0055001-1: PCB Pin, Swage Mount, TH; Manufacturer: Mill-Max; CNHeader: FALSE; Green_Lifecycle: Active; Green_REACh: Passed; CompType: PCB Pin
P2 = CMP-0055152-1: Test Point, Miniature, SMT; Manufacturer: Keystone; CNHeader: FALSE; Green_Lifecycle: Active; Green_REACh: Passed; CT: TRUE
P4 P7 = CMP-0055003-1: PCB Pin, Swage Mount, TH; Manufacturer: Mill-Max; CNHeader: FALSE; Green_Lifecycle: Active; Green_REACh: Passed; CompType: PCB Pin
Q1 = CMP-0000447-1: Transistor, NPN, 100 V, 1 A, SOT-223; Manufacturer: Diodes Incorporated; TaMax_C: 150°C; Value2: 100; Value1: 1 A; Vcesat1_V: 95mV; SizeX_mm: 6.5; SizeY_mm: 7; TaMin_C: -55°C; IcRated_A: 3.5A; CompType: BJT; SizeZ_mm: 1.6; HfeMax: 200; SizeArea_mm2: 45.5; NPN: 1; Vceo_V: 100V; PNP: 0; AEC Category: Q101; SizeAreaWB_mm2: 76.5; U/M: EA
Q3 = CMP-0000384-2: Transistor, NPN, 45 V, 1 A, SOT-89; Manufacturer: Diodes Inc.; TaMax_C: 150°C; Value1: 1 A; Vcesat1_V: 80mV; SizeX_mm: 4.1; SizeY_mm: 4.5; TaMin_C: -55°C; IcRated_A: 1A; CompType: BJT; SizeZ_mm: 1.5; SizeArea_mm2: 18.45; NPN: 1; Vceo_V: 45V; PNP: 0; AEC Category: Q101; SizeAreaWB_mm2: 28.05; U/M: EA
Q6-Q9 = CMP-0077247-1: MOSFET N-CHANNEL 60V 64A 8TDSON; Manufacturer: Infineon; QgTyp_nC: 10nC @ 4.5V; Vgs_V: 20V; AEC Qualified: No; ChMode: False; IdsMax_A: 15A; Symbol Name: SYM-BSC065N06LS5ATMA1; Rdson45_ohm: 5.3m; SizeZ_mm: 1.1mm
Q12 Q13 = CMP-DMN5L06DMK-7: MOSFET, 2-CH, N-CH, 50 V, 0.305 A, AEC-Q101, SOT-26; Alternate Manufacturer: None; Manufacturer: Diodes Inc.; SizeZ_mm: 1.1; ChType: N; VdsMax_V: 50V; SizeX_mm: 3.0; SizeY_mm: 2.2; Vgs_V: 20V; AEC Qualified: Y; AEC Category: Q101; IdsMax_A: 305mA; U/M: EA
R3 = CMP-0020622-3: RES, 100 k, 5%, 0.125 W, AEC-Q200 Grade 0, 0805; Manufacturer: Panasonic; Power_W: 125mW; TempCo: 200 ppm/C; Value: 100k; EIA_Code: E24; SizeX_mm: 2; SizeY_mm: 1.25; SizeZ_mm: 1.45; Value2: 0.125W; SizeArea_mm2: 2.5; AEC Qualified: Y; VDC_V: 150V; AEC Category: Q200; AEC Grade: 0; SizeAreaWB_mm2: 6.75
R4 = CMP-0020740-3: RES, 5.1 k, 5%, 0.125 W, AEC-Q200 Grade 0, 0805; Manufacturer: Panasonic; Power_W: 125mW; TempCo: 200 ppm/C; Value_Code: 5k10; Value: 5.1k; EIA_Code: E24; SizeX_mm: 2; SizeY_mm: 1.25; SizeZ_mm: 1.45; Value2: 0.125W; SizeArea_mm2: 2.5; AEC Qualified: Y; VDC_V: 150V; AEC Category: Q200; AEC Grade: 0; SizeAreaWB_mm2: 6.75
R6 = CMP-0021734-3: RES, 49.9 k, 1%, 0.125 W, AEC-Q200 Grade 0, 0805; Manufacturer: Panasonic; Power_W: 125mW; TempCo: 100 ppm/C; Value_Code: 49k9; Value: 49.9k; EIA_Code: E96; SizeX_mm: 2; SizeY_mm: 1.25; SizeZ_mm: 1.45; Value2: 0.125W; SizeArea_mm2: 2.5; AEC Qualified: Y; AEC Category: Q200; AEC Grade: 0; SizeAreaWB_mm2: 6.75
R7 = CMP-0022136-4: RES, 1.91 k, 1%, 0.1 W, AEC-Q200 Grade 0, 0603; Manufacturer: Vishay-Dale; Power_W: 100mW; TempCo: 100 ppm/C; Value_Code: 1k91; Value: 1.91k; EIA_Code: E96; SizeX_mm: 1.6; SizeY_mm: 0.8; SizeZ_mm: 1; Value2: 0.1W; SizeArea_mm2: 1.28; AEC Qualified: Y; VDC_V: 75V; AEC Category: Q200; AEC Grade: 0
R8 = CMP-0020668-3: RES, 20, 5%, 0.125 W, AEC-Q200 Grade 0, 0805; Manufacturer: Panasonic; Power_W: 125mW; TempCo: 200 ppm/C; Value_Code: 20R0; Value: 20; EIA_Code: E24; SizeX_mm: 2; SizeY_mm: 1.25; SizeZ_mm: 1.45; Value2: 0.125W; SizeArea_mm2: 2.5; AEC Qualified: Y; VDC_V: 150V; AEC Category: Q200; AEC Grade: 0; SizeAreaWB_mm2: 6.75
R9 = CMP-0022981-5: RES, 2.05 k, 1%, 0.1 W, 0603; Manufacturer: Yageo; Power_W: 100mW; TempCo: 100 ppm/C; Value_Code: 2k05; Value: 2.05k; EIA_Code: E96; SizeX_mm: 1.6; SizeY_mm: 0.8; SizeZ_mm: 1; Value2: 0.1W; SizeArea_mm2: 1.28; AEC Qualified: N; VDC_V: 75V; AEC Category: Q200; SizeAreaWB_mm2: 4.68
R11 = CMP-0016046-3: RES, 100, 5%, 0.75 W, AEC-Q200 Grade 0, 2010; Manufacturer: Vishay-Dale; Power_W: 750mW; TempCo: 200 ppm/C; Value_Code: 100R; Value: 100; EIA_Code: E24; SizeX_mm: 5; SizeY_mm: 2.5; SizeZ_mm: 1.66; Value2: 0.75W; SizeArea_mm2: 12.5; AEC Qualified: Y; VDC_V: 400V; AEC Grade: 0; AEC Category: Q200
R13 = CMP-0022131-4: RES, 1.69 k, 1%, 0.1 W, AEC-Q200 Grade 0, 0603; Manufacturer: Vishay-Dale; Power_W: 100mW; TempCo: 100 ppm/C; Value_Code: 1k69; Value: 1.69k; EIA_Code: E96; SizeX_mm: 1.6; SizeY_mm: 0.8; SizeZ_mm: 1; Value2: 0.1W; SizeArea_mm2: 1.28; AEC Qualified: Y; VDC_V: 75V; AEC Category: Q200; AEC Grade: 0
R14 = CMP-0025762-4: RES, 24 k, 5%, 0.1 W, AEC-Q200 Grade 0, 0603; Manufacturer: Vishay-Dale; Power_W: 100mW; TempCo: 200 ppm/C; Value_Code: 24k0; Value: 24k; EIA_Code: E24; SizeX_mm: 1.6; SizeY_mm: 0.8; SizeZ_mm: 1; Value2: 0.1W; SizeArea_mm2: 1.28; AEC Qualified: Y; VDC_V: 75V; AEC Category: Q200; AEC Grade: 0
R15 = CMP-0022324-4: RES, 30.1 k, 1%, 0.1 W, AEC-Q200 Grade 0, 0603; Manufacturer: Vishay-Dale; Power_W: 100mW; TempCo: 100 ppm/C; Value_Code: 30k1; Value: 30.1k; EIA_Code: E96; SizeX_mm: 1.6; SizeY_mm: 0.8; SizeZ_mm: 1; Value2: 0.1W; SizeArea_mm2: 1.28; AEC Qualified: Y; VDC_V: 75V; AEC Category: Q200; AEC Grade: 0
R16 = CMP-0022204-4: RES, 20.0 k, 1%, 0.1 W, AEC-Q200 Grade 0, 0603; Manufacturer: Vishay-Dale; Power_W: 100mW; TempCo: 100 ppm/C; Value_Code: 20k0; Value: 20.0k; EIA_Code: E96; Res_ohm: 20k; SizeX_mm: 1.6; SizeY_mm: 0.8; SizeZ_mm: 1; Value2: 0.1W; SizeArea_mm2: 1.28; AEC Qualified: Y; VDC_V: 75V; AEC Category: Q200; AEC Grade: 0
R17 = CMP-0015868-3: RES, 10 k, 5%, 1 W, AEC-Q200 Grade 0, 2512; Manufacturer: Vishay-Dale; Power_W: 1W; TempCo: 200 ppm/C; Value_Code: 10k0; Value: 10k; EIA_Code: E24; SizeX_mm: 6.3; SizeY_mm: 3.2; SizeZ_mm: 0.71; SizeArea_mm2: 20.16; AEC Qualified: Y; VDC_V: 500V; AEC Grade: 0; AEC Category: Q200
R18 = CMP-0021917-2: RES, 3.24, 1%, 0.125 W, 0805; Manufacturer: Yageo America; Power_W: 125mW; TempCo: 200 ppm/C; Value_Code: 3R24; U/M: EA; Value: 3.24; EIA_Code: E96; SizeX_mm: 2; SizeY_mm: 1.25; SizeZ_mm: 1.45; Value2: 0.125W; SizeArea_mm2: 2.5; VDC_V: 150V; AEC Category: Q200
R19 = CMP-0022707-2: RES, 49.9, 1%, 0.1 W, AEC-Q200 Grade 0, 0603; Manufacturer: Panasonic; Power_W: 100mW; Value_Code: 49R9; U/M: EA; Value: 49.9; EIA_Code: E96; TempCo: 100 ppm/C; SizeX_mm: 1.6; SizeY_mm: 0.8; SizeZ_mm: 1; Value2: 0.1W; SizeArea_mm2: 1.28; AEC Qualified: Y; AEC Grade: 0; AEC Category: Q200
R22 = CMP-0023234-4: RES, 680 k, 1%, 0.1 W, 0603; Manufacturer: Yageo; Power_W: 100mW; TempCo: 100 ppm/C; Value: 680k; SizeX_mm: 1.6; SizeY_mm: 0.8; SizeZ_mm: 1; Value2: 0.1W; SizeArea_mm2: 1.28; AEC Qualified: N; VDC_V: 75V; AEC Category: Q200; SizeAreaWB_mm2: 4.68
R23 = CMP-0022446-5: RES, 499, 1%, 0.1 W, AEC-Q200 Grade 0, 0603; Manufacturer: Vishay-Dale; Power_W: 100mW; TempCo: 100 ppm/C; Value_Code: 499R; Value: 499; EIA_Code: E96; SizeX_mm: 1.6; SizeY_mm: 0.8; SizeZ_mm: 1; Value2: 0.1W; SizeArea_mm2: 1.28; AEC Qualified: Y; VDC_V: 75V; AEC Category: Q200; AEC Grade: 0
R24 = CMP-0022509-4: RES, 5.11 k, 1%, 0.1 W, AEC-Q200 Grade 0, 0603; Manufacturer: Vishay-Dale; Power_W: 100mW; TempCo: 100 ppm/C; Value_Code: 5k11; Value: 5.11k; EIA_Code: E96; SizeX_mm: 1.6; SizeY_mm: 0.8; SizeZ_mm: 1; Value2: 0.1W; SizeArea_mm2: 1.28; AEC Qualified: Y; VDC_V: 75V; AEC Category: Q200; AEC Grade: 0
R27 = CMP-0025815-4: RES, 47, 5%, 0.25 W, AEC-Q200 Grade 0, 0603; Manufacturer: Vishay-Dale; Power_W: 100mW; TempCo: 200 ppm/C; Value_Code: 47R0; Value: 47; EIA_Code: E24; SizeX_mm: 1.6; SizeY_mm: 0.8; SizeZ_mm: 1; Value2: 0.25W; SizeArea_mm2: 1.28; AEC Qualified: Y; VDC_V: 75V; AEC Category: Q200; AEC Grade: 0
R28 R100 = CMP-0022735-5: RES, 100 k, 1%, 0.1 W, 0603; Manufacturer: Yageo; Power_W: 100mW; TempCo: 100 ppm/C; Value: 100k; EIA_Code: E96; SizeX_mm: 1.6; SizeY_mm: 0.8; SizeZ_mm: 1; Value2: 0.1W; SizeArea_mm2: 1.28; AEC Qualified: N; VDC_V: 75V; AEC Category: Q200; SizeAreaWB_mm2: 4.68
R29 = CMP-0022066-4: RES, 15.0 k, 1%, 0.1 W, AEC-Q200 Grade 0, 0603; Manufacturer: Vishay-Dale; Power_W: 100mW; TempCo: 100 ppm/C; Value_Code: 15k0; Value: 15.0k; EIA_Code: E96; Res_ohm: 15k; SizeX_mm: 1.6; SizeY_mm: 0.8; SizeZ_mm: 1; Value2: 0.1W; SizeArea_mm2: 1.28; AEC Qualified: Y; VDC_V: 75V; AEC Category: Q200; AEC Grade: 0
R30 = CMP-0022134-4: RES, 1.82 k, 1%, 0.1 W, AEC-Q200 Grade 0, 0603; Manufacturer: Vishay-Dale; Power_W: 100mW; TempCo: 100 ppm/C; Value_Code: 1k82; Value: 1.82k; EIA_Code: E96; SizeX_mm: 1.6; SizeY_mm: 0.8; SizeZ_mm: 1; Value2: 0.1W; SizeArea_mm2: 1.28; AEC Qualified: Y; VDC_V: 75V; AEC Category: Q200; AEC Grade: 0
R33 = CMP-0022923-5: RES, 22.1 k, 1%, 0.1 W, 0603; Manufacturer: Yageo; Power_W: 100mW; TempCo: 100 ppm/C; Value_Code: 22k1; Value: 22.1k; EIA_Code: E96; SizeX_mm: 1.6; SizeY_mm: 0.8; SizeZ_mm: 1; Value2: 0.1W; SizeArea_mm2: 1.28; AEC Qualified: N; VDC_V: 75V; AEC Category: Q200; SizeAreaWB_mm2: 4.68
R34-R36 = CMP-0021998-4: RES, 10.0 k, 1%, 0.1 W, AEC-Q200 Grade 0, 0603; Manufacturer: Vishay-Dale; Power_W: 100mW; TempCo: 100 ppm/C; Value_Code: 10k0; Value: 10.0k; EIA_Code: E96; Res_ohm: 10k; SizeX_mm: 1.6; SizeY_mm: 0.8; SizeZ_mm: 1; Value2: 0.1W; SizeArea_mm2: 1.28; AEC Qualified: Y; VDC_V: 75V; AEC Category: Q200; AEC Grade: 0
R37 = CMP-0025697-4: RES, 0, 5%, 0.1 W, AEC-Q200 Grade 0, 0603; Manufacturer: Vishay-Dale; Power_W: 100mW; TempCo: 200 ppm/C; Value_Code: 0000; Value: 0; EIA_Code: E24; SizeX_mm: 1.6; SizeY_mm: 0.8; SizeZ_mm: 1; Value2: 0.1W; SizeArea_mm2: 1.28; AEC Qualified: Y; VDC_V: 75V; AEC Category: Q200
T1 = CMP-0030387-2: High Frequency Planar Transformer; Manufacturer: Coilcraft; LeakageInd_H: TBD; Ind_H: 23.6µH; Lp: 23.6u
T2 = CMP-0030386-2: SMT Current Sense Tranformer; Manufacturer: Pulse Engineering; Green_Lifecycle: Not Set; Green_REACh: Incomplete; CompType: Transformer; Rsec1_ohm: 5.5
U1 = CMP-0071922-2: Full-Bridge PWM Controller with Integrated MOSFET Drivers, 28-pin TSSOP-EP, 2500 Reel; Manufacturer: Texas Instruments; PackageTopMarking: NSUZXYTTE#*LM5045*MH; CompType: Switcher; PowerWise: Y
U3 = CMP-0006166-3: Optocoupler, 3.75 kV, 80-160% CTR, SMT; Manufacturer: Vishay-Semiconductor; CTR (Max): 160%; SizeAreaWB_mm2: 43.65; CTR (Min): 80%; SizeZ_mm: 2.3; SizeX_mm: 7; SizeY_mm: 2.85; SizeArea_mm2: 19.95; Voltage_Isolation_Vrms: 3.75kV
U4 = CMP-0084708-1: RRIO, High Output Current & Unlimited Cap Load Op Amp, DBV0005A (SOT-23-5); Alternate Manufacturer: Texas Instruments; SizeY_mm: 2.9; SizeAreaWB_mm2: 14.82; AEC Category: Q200; Rating: Catalog; SizeZ_mm: 1.45; SizeArea_mm2: 8.12; AEC Qualified: N; CompType: IC; SizeX_mm: 2.8
U5 = CMP-0033063-1: Precision Micropower Shunt Voltage Reference, 0.2% accuracy, 1.2 V, 15 ppm / degC, 12 mA, -40 to 85 degC, 3-pin SOT-23 (DBZ), Green (RoHS & no Sb/Br); Manufacturer: Texas Instruments; Rating: Catalog; Initial Accuracy @ 25/deg C(%): 0.2; Min Iz for Regulation(uA): 60; Iout/Iz(Max)(mA): 12; Temp Coeff(Typ)(ppm/ degree C): 15; VO(V): 1.2; Temp Coeff(Max)(ppm/ degree C): 100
